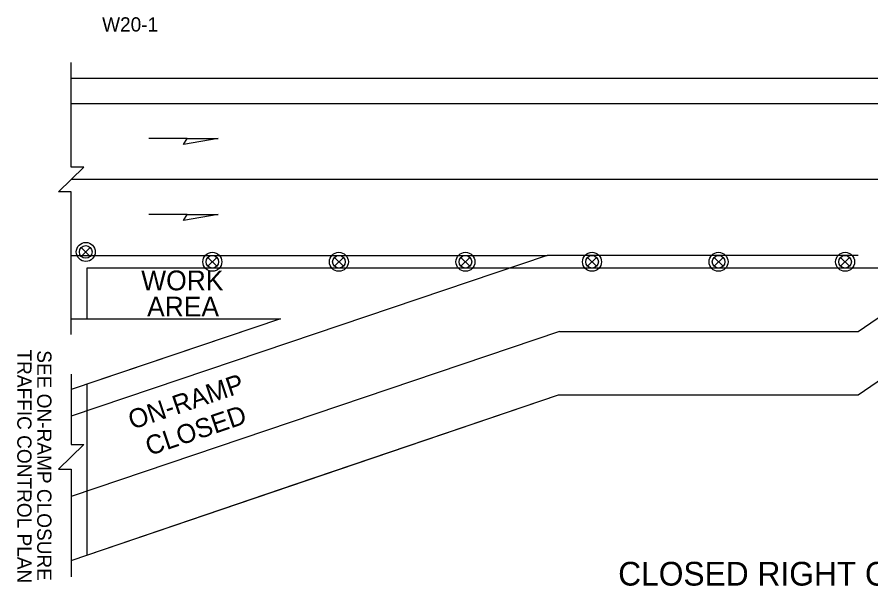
# Model space of a CAD drawing. Extents: x 99999.1 to 100055.7, y 99995 to 100013.2.
# Drawn here: x 100027.922 to 100032.24, y 100001.799 to 100004.676 of the extents above; entities that cross this region are included whole.
import ezdxf

# ---------------------------------------------------------------- set-up
doc = ezdxf.new("R2010")
doc.units = 0
for name, color, linetype in [('RD_MK_LineEdgeYellow', 7, 'Continuous'), ('RD_MK_LineLane', 7, 'Continuous'), ('SH_DE_DetailHeading2Text', 7, 'Continuous'), ('TR_SN_ConstructionSigns', 7, 'Continuous'), ('TR_WZ_TrafficSafetyDrum', 7, 'Continuous'), ('TR_WZ_WorkAreaLabel', 7, 'Continuous'), ('TR_WZ_WorkZoneDetails', 7, 'Continuous')]:
    doc.layers.add(name, color=color, linetype=linetype)

msp = doc.modelspace()

# ---------------------------------------------------------------- linework, layer by layer
at = {"layer": 'RD_MK_LineEdgeYellow'}
for p, q in [((100028.195, 100004.238), (100035.43, 100004.238)), ((100028.195, 100003.47), (100029.2533, 100003.47)), ((100032.1758, 100003.086), (100032.7368, 100003.47)), ((100030.6655, 100003.086), (100028.195, 100002.2517)), ((100030.6655, 100003.086), (100032.1758, 100003.086)), ((100029.2943, 100003.0282), (100028.195, 100002.657))]:
    msp.add_line(p, q, dxfattribs=at)
at = {"layer": 'RD_MK_LineLane'}
for points in [[(100035.43, 100003.854), (100028.195, 100003.854)], [(100032.1758, 100003.47), (100030.6024, 100003.47)]]:
    msp.add_lwpolyline(points, dxfattribs=at)
at = {"layer": 'TR_WZ_TrafficSafetyDrum'}
for p, q in [((100028.2468, 100003.5106), (100028.292, 100003.4653)), ((100028.292, 100003.5106), (100028.2468, 100003.4653)), ((100028.8868, 100003.4606), (100028.932, 100003.4153)), ((100028.932, 100003.4606), (100028.8868, 100003.4153)), ((100029.5268, 100003.4606), (100029.572, 100003.4153)), ((100029.572, 100003.4606), (100029.5268, 100003.4153)), ((100030.1668, 100003.4606), (100030.212, 100003.4153)), ((100030.212, 100003.4606), (100030.1668, 100003.4153)), ((100030.8068, 100003.4606), (100030.852, 100003.4153)), ((100030.852, 100003.4606), (100030.8068, 100003.4153)), ((100031.4468, 100003.4606), (100031.492, 100003.4153)), ((100031.492, 100003.4606), (100031.4468, 100003.4153)), ((100032.0868, 100003.4606), (100032.132, 100003.4153)), ((100032.132, 100003.4606), (100032.0868, 100003.4153))]:
    msp.add_line(p, q, dxfattribs=at)
for centre, radius in [((100028.2694, 100003.488), 0.048), ((100028.2694, 100003.488), 0.048), ((100028.2694, 100003.488), 0.032), ((100028.9094, 100003.438), 0.048), ((100028.9094, 100003.438), 0.048), ((100028.9094, 100003.438), 0.032), ((100029.5494, 100003.438), 0.048), ((100029.5494, 100003.438), 0.048), ((100029.5494, 100003.438), 0.032), ((100030.1894, 100003.438), 0.048), ((100030.1894, 100003.438), 0.048), ((100030.1894, 100003.438), 0.032), ((100030.8294, 100003.438), 0.048), ((100030.8294, 100003.438), 0.048), ((100030.8294, 100003.438), 0.032), ((100031.4694, 100003.438), 0.048), ((100031.4694, 100003.438), 0.048), ((100031.4694, 100003.438), 0.032), ((100032.1094, 100003.438), 0.048), ((100032.1094, 100003.438), 0.048), ((100032.1094, 100003.438), 0.032)]:
    msp.add_circle(centre, radius, dxfattribs=at)
at = {"layer": 'TR_WZ_WorkZoneDetails'}
for p, q in [((100028.195, 100004.366), (100035.43, 100004.366)), ((100028.782, 100004.0614), (100028.5891, 100004.0614)), ((100028.782, 100003.6774), (100028.5891, 100003.6774)), ((100029.2533, 100003.47), (100030.6024, 100003.47)), ((100030.6024, 100003.47), (100029.2943, 100003.0282)), ((100028.195, 100003.15), (100029.2533, 100003.15)), ((100029.2533, 100003.15), (100028.195, 100002.7929)), ((100032.1758, 100002.766), (100032.7368, 100003.15)), ((100028.195, 100001.928), (100030.6601, 100002.766)), ((100030.6601, 100002.766), (100032.1758, 100002.766))]:
    msp.add_line(p, q, dxfattribs=at)
for points in [[(100028.195, 100003.07), (100028.195, 100003.792), (100028.131, 100003.792), (100028.259, 100003.9159), (100028.195, 100003.9159), (100028.195, 100004.446)], [(100028.195, 100002.8701), (100028.195, 100002.5136), (100028.259, 100002.5136), (100028.131, 100002.3897), (100028.195, 100002.3897), (100028.195, 100001.8453)]]:
    msp.add_lwpolyline(points, dxfattribs=at)
for points in [[(100028.9392, 100004.0614), (100028.7641, 100004.0305), (100028.782, 100004.0614)], [(100028.9392, 100003.6774), (100028.7641, 100003.6465), (100028.782, 100003.6774)], [(100028.275, 100003.406), (100028.275, 100003.15), (100029.2533, 100003.15), (100028.275, 100002.8199), (100028.275, 100002.8199), (100028.275, 100002.8199), (100028.275, 100001.9552), (100028.275, 100001.9552), (100028.275, 100001.9552), (100029.3341, 100002.3152), (100030.6601, 100002.766), (100032.1758, 100002.766), (100032.7368, 100003.15), (100035.35, 100003.15), (100035.35, 100003.406)]]:
    msp.add_lwpolyline(points, close=True, dxfattribs=at)

# ---------------------------------------------------------------- texts
at = {"layer": 'SH_DE_DetailHeading2Text'}
msp.add_text('CLOSED RIGHT ON-RAMP DETAIL', height=0.12, rotation=360, dxfattribs=at).set_placement((100030.9618, 100001.8009))
at = {"layer": 'TR_SN_ConstructionSigns'}
msp.add_text('W20-1', height=0.072, rotation=360, dxfattribs=at).set_placement((100028.352, 100004.6025))
at = {"layer": 'TR_WZ_WorkAreaLabel'}
for s, p in [('WORK', (100028.5496, 100003.294)), ('AREA', (100028.5793, 100003.1619))]:
    msp.add_text(s, height=0.1, dxfattribs=at).set_placement(p)
at = {"layer": 'TR_WZ_WorkZoneDetails'}
for s, height, rotation, p in [('TRAFFIC CONTROL PLAN', 0.072, 270, (100027.923, 100002.9948)), ('SEE ON-RAMP CLOSURE', 0.072, 270, (100028.0238, 100002.9908)), ('ON-RAMP', 0.096, 18.659, (100028.5039, 100002.589)), ('ON-RAMP', 0.096, 18.659, (100028.5039, 100002.589)), ('CLOSED', 0.096, 18.659, (100028.5907, 100002.4562)), ('CLOSED', 0.096, 18.659, (100028.5907, 100002.4562))]:
    msp.add_text(s, height=height, rotation=rotation, dxfattribs=at).set_placement(p)

doc.saveas('drawing.dxf')
